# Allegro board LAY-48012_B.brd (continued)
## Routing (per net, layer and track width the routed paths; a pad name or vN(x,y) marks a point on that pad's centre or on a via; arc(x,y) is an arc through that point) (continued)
DAC_SDIN3: length 7.5
  BOTTOM w0.152: R19.2 24.99,32.89 24.99,33.4 26.9,35.31 27.41,35.31 27.71,35 U3.15
DAC_SDIN4: length 6.4
  BOTTOM w0.152: U3.14 28.21,35.26 27.66,35.81 26.64,35.81 24.74,33.91 R20.2
DC_GPIO1: length 3.6
  TOP w0.152: J1.21 22.71,6.16 22.71,8.76 R4.1
DC_I2C_SCL: length 51.3
  BOTTOM w0.152: 39.85,33.78 39.85,32.89 40.74,32 40.74,28.84 42.65,26.94 42.65,17.46 45.84,14.27 45.84,3.45 44.4,2.01 33.02,2.01 31.65,3.38 31.65,5.1 J1.13
DC_I2C_SDA: length 56.2
  BOTTOM w0.152: J1.15 29.65,5.1 29.65,3.35 31.34,1.65 44.68,1.65 46.33,3.3 46.33,14.32 43.03,17.62 43.03,27.09 41.12,29 41.12,33.4 39.85,34.67 39.85,35.56
DC_I2S1_MCLK: length 30.7
  BOTTOM w0.152: R9.1 32.87,28.83 34.26,27.43 39.09,27.43 40.61,25.91 40.61,16.49 43.03,14.08 43.03,6.48 J1.1
DC_I2S1_RX_BCLK: length 35.5
  BOTTOM w0.152: R10.1 35.28,28.45 38.96,28.45 41.25,26.16 41.25,16.76 44.17,13.84 44.17,5.36 43.91,5.1 39.65,5.1 J1.5
DC_I2S1_RX_D0: length 33.7
  BOTTOM w0.152: J1.11 31.5,7.24 27.91,7.24 27.34,7.81 25.06,7.81 22.07,10.79 22.07,27.05 23.34,28.32 23.98,28.32 25.37,29.72 R12.1
DC_I2S1_RX_SYNC: length 46.9
  BOTTOM w0.152: J1.9 34.65,6.1 35.79,7.24 37.06,7.24 37.65,6.65 37.65,3.35 38.07,2.92 43.92,2.92 44.81,3.81 44.81,14.1 41.88,17.02 41.88,26.42 39.22,29.08 35.66,29.08 R11.1
DC_I2S1_TX_BCLK: length 28
  BOTTOM w0.152: R15.1 21.69,32.51 21.69,29.72 19.85,27.88 19.85,6.89 J1.23
DC_I2S1_TX_D0: length 38.7
  BOTTOM w0.152: R17.1 22.33,32.13 22.33,29.46 20.42,27.56 20.42,9.4 21.65,8.17 21.65,3.35 22.07,2.92 25.25,2.92 25.65,3.32 25.65,5.1 J1.17
DC_I2S1_TX_D1: length 34.2
  TOP w0.152: v1(25.88,29.46) v1(24.36,29.46)
  BOTTOM w0.152: R14.1 26.39,29.97 v1(25.88,29.46) ; R18.1 v1(24.36,29.46) 23.72,28.83 23.22,28.83 21.69,27.3 21.69,10.54 24.88,7.35 27.17,7.35 27.65,6.87 27.65,5.1 J1.18
DC_I2S1_TX_D2: length 31.3
  TOP w0.152: v1(25.25,28.83) 23.98,28.83 v1(23.34,29.46)
  BOTTOM w0.152: R19.1 v1(23.34,29.46) 21.25,27.37 21.25,10.35 24.65,6.95 J1.19 ; v1(25.25,28.83) 26.01,28.83 R81.1
DC_I2S1_TX_D3: length 31.7
  BOTTOM w0.152: J1.20 23.65,5.1 23.65,6.93 20.87,9.72 20.87,27.5 22.71,29.34 22.71,31.5 R20.1
DC_I2S1_TX_SYNC: length 40.5
  BOTTOM w0.152: R16.1 21.06,29.97 19.28,28.19 19.28,3.68 20.55,2.41 26.96,2.41 J1.16
DC_INT: length 42
  TOP w0.152: v1(42.39,12.19) v1(46.84,12.19)
  BOTTOM w0.152: J1.3 42.39,7.84 v1(42.39,12.19) ; U3.61 38.17,37.5 R24.1 39.47,36.2 40.11,36.2 41.63,34.67 41.63,29.08 43.41,27.3 43.41,17.91 46.84,14.48 v1(46.84,12.19)
DC_RESET: length 52
  BOTTOM w0.152: J1.7 35.65,5.1 35.65,3.32 36.55,2.41 44.17,2.41 45.31,3.56 45.31,14.26 42.27,17.31 42.27,26.67 39.34,29.59 36.04,29.59 35.15,30.48 35.15,31.24 R26.1 35.41,32.26 34.39,32.26 33.71,32.94 U3.3
MCLK_IN: length 8
  BOTTOM w0.152: R9.2 29.44,28.83 28.42,29.84 28.42,31.37 30.21,33.16 U3.10
MICIN_1: length 10.5
  BOTTOM w0.254: J10.4 57.23,35.79 TVS12.2 R72.1 57.12,38.48 56.87,38.73 R84.2 R71.1 R38.1 56.87,42.42 C41.1
MICIN_2: length 10.9
  BOTTOM w0.254: J11.4 58.46,24.36 TVS13.2 56.58,23.79 R74.1 55.98,23.37 C43.1 54.2,22.99 R73.1 R39.1 R85.2
MUTEC_OUT: length 3.7
  TOP w0.152: v2(28.17,43.31) 27.91,43.56 R33.1
  BOTTOM w0.152: U3.35 28.21,43.35 v2(28.17,43.31)
SCL_CCLK: length 7
  BOTTOM w0.152: R21.2 38.71,32.89 37.82,33.78 36.93,33.78 35.28,35.43 35.28,36.2 35.59,36.5 U3.63
SDA_CDOUT: length 2.3
  BOTTOM w0.152: U3.64 38.4,36 R22.2
N16325068: length 4.9
  TOP w0.381: 25.45,26.16 J5.2 ; J5.2 26.52,25.09 ; J5.2 26.52,27.23 ; 27.39,29.63 FB3.1 ; FB3.1 27.39,30.82 ; FB3.1 26.86,30.23
N16325522: length 3
  BOTTOM w0.152: v2(28.17,40) 28.17,40 U3.25
N16325540: length 3
  BOTTOM w0.152: v2(28.17,41.66) 28.01,41.5 U3.28
N16325558: length 2.4
  BOTTOM w0.152: v2(22.83,41.91) 22.93,42 U3.29
N16325576: length 3.4
  BOTTOM w0.152: v2(23.98,45.97) 23.98,43.94 24.42,43.5 U3.32
N16325594: length 2.3
  BOTTOM w0.152: v2(25.76,45.97) 26.14,46.36 26.9,46.36 27.21,46.04 U3.33
N16325612: length 3
  BOTTOM w0.152: U3.37 29.21,43.79 v2(30.07,42.93)
N16325620: length 3.9
  BOTTOM w0.152: v2(31.85,42.93) 31.09,42.93 29.71,44.3 U3.38
N16325628: length 4.1
  BOTTOM w0.152: U3.41 31.21,44.45 32.74,42.93 v2(33.63,42.93)
N16325638: length 12.6
  BOTTOM w0.254: U3.55 41.24,40.5 42.01,41.27 42.01,44.96 42.65,45.59 C25.1 43.29,47.36 C26.1
N16325678: length 10.5
  BOTTOM w0.254: U3.54 40.98,41 41.5,41.52 C32.1 41.5,46.87 C33.1
N16325718: length 6
  BOTTOM w0.152: C23.1 C24.1 30.45,48.01 30.96,47.5 31.85,47.5 32.21,47.14 U3.43
N16334310: length 2.2
  BOTTOM w0.254: 52.04,68.07 52.04,65.91
N16334338: length 16.3
  BOTTOM w0.254: C51.2 37.54,65.25 40.36,68.07 R49.2
N16334434: length 2.2
  BOTTOM w0.254: R52.1 R53.2 R51.2
N16334446: length 2.4
  BOTTOM w0.254: C54.2 R52.2
N16339295: length 3.1
  BOTTOM w0.254: R58.1 R60.1 C61.2
N16339361: length 4.2
  BOTTOM w0.254: 13.69,36.83 13.69,38.86 13.41,39.14 C65.2
N16339413: length 4.3
  BOTTOM w0.254: C58.2 R57.1 R55.1
N16339465: length 3.3
  BOTTOM w0.254: R59.1 R61.1 C62.2
N16339521: length 3.3
  BOTTOM w0.254: R63.1 R65.1 C66.2
N16339573: length 4.9
  BOTTOM w0.254: R54.1 R56.1 12.93,24.77 13.41,25.25 C57.2
N16343600: length 1.5
  TOP w0.152: D1.A 25.51,10.67 R1.2
N16357095: length 3.5
  TOP w0.152: R83.2 R4.2 R7.1 21.04,10.43 Q2.1
N16357107: length 4.3
  TOP w0.152: R5.1 R2.2 22.71,13.72 22.64,13.78 Q2.3
N16357127: length 7.8
  TOP w0.381: J2.1 32.61,12.57 28.4,12.57 Q1.2 26.83,12.89 R2.1
N16357135: length 5.1
  TOP w0.152: R5.2 26.07,14.79 Q1.1 28.23,14.79 29.06,15.62 C13.1
N16357758: length 5.4
  TOP w0.152: U1.4 34.33,21.9 34.77,21.46 R3.2 R6.1
N16357876: length 10.3
  TOP w0.381: C9.1 39.08,22.23 ; C9.1 37.58,22.23 ; C9.1 38.33,21.6 ; U1.3 36.89,21.9 ; U1.3 36.2,22.46 ; U1.3 35.51,21.9 ; 39.98,22.1 C10.1 40.61,22.61 ; 38.15,19.81 J13.2 ; J13.2 39.22,20.88 ; J13.2 40.28,19.81 ; U1.1 36.89,20.01 ; U1.1 35.51,20.01 ; U1.1 36.2,19.45
N16358335: length 10.2
  TOP w0.381: 21.73,20.72 U2.3 ; U2.3 22.67,20.72 ; U2.3 22.2,21.5 ; 27.23,22.1 J14.2 ; J14.2 28.3,23.17 ; J14.2 29.36,22.1 ; J14.2 28.3,21.03 ; C15.1 25.76,21.21 ; C15.1 26.64,22.1 ; C15.1 C14.1 ; C14.1 24.24,22.1 ; C14.1 24.87,21.21
N16404329: length 5.8
  BOTTOM w0.254: C69.2 R68.1 R66.1
N16404657: length 3.3
  BOTTOM w0.254: 15.09,66.93 C70.2
N16406078: length 8.4
  TOP w0.152: TP1.1 18.64,6.35 19.9,5.1 21.68,5.1 22.65,4.12 J1.22
N16452852: length 6.5
  TOP w0.254: v1(51.41,36.32) J10.2
  BOTTOM w0.254: v1(51.41,36.32) 55.47,36.32 R72.2
N16452871: length 6.4
  TOP w0.254: v1(51.54,39.62) 51.41,39.75 J10.3
  BOTTOM w0.254: v1(51.54,39.62) 52.43,39.62 52.68,39.88 R71.2
N16456970: length 12.4
  TOP w0.254: TP18.1 16.23,28.19 12.55,31.88 8.74,31.88 8.43,31.57 J6.5
N16456974: length 10.2
  TOP w0.254: J6.6 8.43,22.02 9.02,21.44 13.28,21.44 15.21,23.37 TP19.1
N16456978: length 16.6
  TOP w0.254: J6.4 4.31,29.23 7.59,32.51 13.44,32.51 TP20.1
N16457195: length 12.4
  TOP w0.254: TP21.1 16.23,39.62 12.55,43.31 8.74,43.31 8.43,43 J7.5
N16457199: length 9.9
  TOP w0.254: J7.6 8.43,33.58 8.86,33.15 13.44,33.15 15.09,34.8 TP22.1
N16457203: length 16.6
  TOP w0.254: J7.4 4.82,40.66 8.1,43.94 13.44,43.94 TP23.1
N16457422: length 12.4
  TOP w0.254: J8.5 8.43,54.43 8.74,54.74 12.55,54.74 16.23,51.05 TP24.1
N16457426: length 9.9
  TOP w0.254: J8.6 8.43,45.01 8.86,44.58 14.58,44.58 TP25.1
N16457430: length 16.6
  TOP w0.254: J8.4 4.44,52.09 7.72,55.37 13.44,55.37 TP26.1
N16457651: length 12.4
  TOP w0.254: TP27.1 16.23,62.48 12.55,66.17 8.74,66.17 8.43,65.86 J9.5
N16457655: length 9.9
  TOP w0.254: TP28.1 14.58,56.01 8.86,56.01 8.43,56.44 J9.6
N16457659: length 16.6
  TOP w0.254: TP29.1 13.44,66.8 7.59,66.8 4.31,63.52 J9.4
N16458067: length 16.6
  TOP w0.254: J12.4 58.37,58.65 55.09,55.37 49.5,55.37 TP32.1
N16458071: length 10
  TOP w0.254: J12.6 54.51,65.74 53.95,66.29 48.49,66.29 TP31.1
N16458075: length 12.4
  TOP w0.254: J12.5 54.51,56.31 54.2,56.01 50.39,56.01 46.71,59.69 TP30.1
N16458447: length 9.4
  TOP w0.254: J11.3 v1(51.41,28.7)
  BOTTOM w0.254: R74.2 56.49,27.05 54.84,28.7 v1(51.41,28.7)
N16458491: length 3.3
  TOP w0.254: v1(52.43,21.21) 52.43,22.23 51.41,23.24 J11.2
  BOTTOM w0.254: v1(52.43,21.21) R73.2
N16475768: length 2
  BOTTOM w0.254: 52.04,53.97 52.04,56.01
N16475784: length 11.9
  BOTTOM w0.254: C73.2 48.26,58.78 R77.2
N16475838: length 2
  BOTTOM w0.254: R80.1 R79.2 R78.2
N16475850: length 2.2
  BOTTOM w0.254: C74.2 R80.2
N16477331: length 16.8
  TOP w0.254: TP35.1 47.73,46.74 50.77,43.69 55.47,43.69 59.01,47.22 J15.4
N16477335: length 9.9
  TOP w0.254: J15.6 54.51,54.31 54.08,54.74 48.36,54.74 TP34.1
N16477339: length 12.5
  TOP w0.254: TP33.1 46.71,48.51 51.03,44.2 53.7,44.2 53.95,44.45 53.95,45.67 J15.5
N16544253: length 70.5
  TOP w0.254: P1.1 29.44,69.47 30.96,67.94 54.58,67.94 56.62,65.91 v1(56.62,62.86)
  BOTTOM w0.254: R84.1 58.9,39.88 58.9,46.23 56.62,48.51 v1(56.62,62.86)
N16544784: length 1.9
  BOTTOM w0.254: R85.1 54.2,17.78 P2.1

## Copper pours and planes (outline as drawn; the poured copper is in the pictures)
AGND on TOP: 62.33,71.63 62.71,71.25 62.71,22.48 62.46,22.23 57.25,22.23 55.98,20.95 55.98,16.38 55.6,16 46.33,16 44.42,17.91 44.42,28.19 42.77,29.84 42.77,35.05 40.11,37.72 34.52,37.72 32.99,39.24 27.91,39.24 27.28,39.88 21.18,39.88 20.29,38.99 20.29,30.86 18.01,28.58 18.01,22.1 16.36,20.45 7.72,20.45 6.2,21.97 0.36,21.97 0.23,22.1 0.23,71.25 0.61,71.63 ; 1 cut-out
AGND on BOTTOM: 62.33,71.63 62.71,71.25 62.71,22.48 62.46,22.23 57.25,22.23 55.98,20.95 55.98,16.38 55.6,16 50.65,16 50.52,16.13 50.52,17.4 50.14,17.78 47.35,17.78 46.33,18.8 44.55,18.8 44.42,18.92 44.42,28.32 42.77,29.97 42.77,35.05 40.61,37.21 38.96,37.21 38.46,37.72 34.52,37.72 32.99,39.24 27.91,39.24 27.28,39.88 21.18,39.88 18.01,36.7 18.01,22.1 16.36,20.45 7.72,20.45 6.2,21.97 0.36,21.97 0.23,22.1 0.23,71.25 0.61,71.63 ; 6 cut-outs
AGND on L2_GND1: 62.33,71.63 62.71,71.25 62.71,22.48 62.46,22.23 57.25,22.23 55.98,20.95 55.98,16.38 54.58,14.99 47.35,14.99 44.42,17.91 44.42,28.32 42.9,29.84 42.9,34.92 40.61,37.21 38.96,37.21 38.46,37.72 34.52,37.72 32.99,39.24 27.91,39.24 27.28,39.88 21.18,39.88 20.29,38.99 20.29,30.86 18.01,28.58 18.01,22.1 16.36,20.45 7.85,20.45 6.2,22.1 0.48,22.1 0.23,22.35 0.23,71.12 0.74,71.63 ; 1 cut-out
AGND on L3_GND2: 62.33,71.63 62.71,71.25 62.71,22.48 62.46,22.23 57.25,22.23 55.98,20.95 55.98,16.38 55.6,16 50.65,16 50.52,16.13 50.52,17.53 50.27,17.78 47.35,17.78 46.33,18.8 44.68,18.8 44.42,19.05 44.42,28.32 42.9,29.84 42.9,34.92 40.11,37.72 34.52,37.72 32.99,39.24 27.91,39.24 27.28,39.88 21.18,39.88 20.29,38.99 20.29,30.86 18.01,28.58 18.01,22.1 16.36,20.45 7.85,20.45 6.2,22.1 0.36,22.1 0.23,22.23 0.23,71.25 0.61,71.63
GND on TOP: 21.31,39.62 27.15,39.62 27.79,38.99 32.87,38.99 34.39,37.47 39.98,37.47 42.52,34.92 42.52,29.72 44.17,28.07 44.17,17.65 46.2,15.62 55.98,15.62 56.36,16 56.36,20.83 57.38,21.84 62.59,21.84 62.71,21.72 62.71,10.79 62.46,10.54 47.45,10.54 47.45,0.51 15.47,0.51 15.47,10.54 0.23,10.54 0.23,21.59 0.36,21.72 6.07,21.72 7.59,20.19 16.48,20.19 18.26,21.97 18.26,28.32 20.55,30.61 20.55,38.86 ; 3 cut-outs
GND on BOTTOM: 34.39,14.86 32.74,13.21 27.03,13.21 27.03,10.29 28.04,9.27 28.04,8.38 27.79,8.13 25.76,8.13 22.45,11.43 22.45,26.92 23.47,27.94 24.23,27.94 25.63,29.34 28.68,29.34 29.69,28.32 32.11,28.32 32.17,28.26 32.8,28.26 34.39,26.67
GND on BOTTOM: 26.39,39.5 27.15,39.5 27.66,38.99 32.87,38.99 34.39,37.47 35.28,37.47 35.41,37.34 35.41,36.83 34.9,36.32 34.9,35.43 34.65,35.18 29.06,35.18 27.53,36.7 27.53,37.72 26.9,38.35 26.39,38.35 26.26,38.48 26.26,39.37
GND on BOTTOM: 16.48,20.19 18.01,21.72 18.64,21.72 18.77,21.59 18.77,3.3 20.42,1.65 30.2,1.65 30.71,1.14 44.93,1.14 46.84,3.05 46.84,15.11 44.04,17.91 44.04,18.41 44.17,18.54 46.08,18.54 47.22,17.4 50.14,17.4 50.27,17.27 50.27,15.75 50.39,15.62 55.98,15.62 56.36,16 56.36,20.7 57.51,21.84 62.59,21.84 62.71,21.72 62.71,10.92 62.33,10.54 47.35,10.54 47.35,10.54 47.35,0.89 47.09,0.64 15.72,0.64 15.6,0.76 15.6,10.41 15.47,10.54 0.23,10.54 0.23,21.59 0.36,21.72 6.07,21.72 7.59,20.19
GND on L2_GND1: 62.59,10.54 47.45,10.54 47.45,0.61 47.35,0.51 15.47,0.51 15.47,10.54 0.36,10.54 0.23,10.67 0.23,21.59 0.36,21.72 6.07,21.72 7.59,20.19 16.48,20.19 18.26,21.97 18.26,28.32 20.55,30.61 20.55,38.86 21.31,39.62 27.15,39.62 27.79,38.99 32.87,38.99 34.39,37.47 39.98,37.47 42.52,34.92 42.52,29.72 44.17,28.07 44.17,17.53 47.09,14.61 54.84,14.61 56.36,16.13 56.36,20.83 57.38,21.84 62.59,21.84 62.71,21.72 62.71,10.67 ; 1 cut-out
GND on L3_GND2: 62.46,10.54 47.45,10.54 47.45,0.51 15.47,0.51 15.47,10.54 0.36,10.54 0.36,21.59 0.48,21.72 6.07,21.72 7.59,20.19 16.48,20.19 18.26,21.97 18.26,28.32 20.55,30.61 20.55,38.86 21.31,39.62 27.03,39.62 27.66,38.99 32.87,38.99 34.39,37.47 39.98,37.47 42.52,34.92 42.52,29.72 44.17,28.07 44.17,18.8 44.42,18.54 46.08,18.54 47.22,17.4 50.14,17.4 50.27,17.27 50.27,15.75 50.39,15.62 55.98,15.62 56.36,16 56.36,20.7 57.51,21.84 62.59,21.84 62.71,21.72 62.71,10.79 ; 1 cut-out
P1V8 on TOP: 37.44,12.32 37.44,8.26 37.19,8 36.55,8 34.65,9.91 34.65,12.32 34.77,12.45 37.31,12.45
P1V8 on BOTTOM: 27.53,19.81 33.25,19.81 33.44,19.62 33.44,16.45 37.44,12.45 37.44,8.51 37.31,8.38 29.31,8.38 27.28,10.41 27.28,19.56
P1V8 on L2_GND1: 39.98,8.26 39.98,3.3 39.6,2.92 31.47,2.92 31.34,3.05 31.34,8.13 31.47,8.26 33.63,8.26 34.65,9.27 34.65,12.32 34.77,12.45 37.57,12.45 37.69,12.32 37.69,10.54
P1V8_S on TOP: 21.95,22.23 21.82,22.1 21.31,22.1 20.93,21.72 20.93,19.68 21.31,19.3 24.23,19.3 24.36,19.18 24.36,16.13 24.23,16 18.77,16 18.64,16.13 18.64,19.56 19.02,19.94 19.02,24.38 19.15,24.51 21.82,24.51 21.95,24.38
P3V3 on TOP: 41.88,12.83 41.88,8.26 42.52,7.62 44.42,7.62 44.68,7.37 44.68,2.92 44.55,2.79 37.57,2.79 37.44,2.92 37.44,7.87 37.57,8 38.71,8 39.85,9.14 39.85,12.83 39.98,12.95 41.76,12.95
P3V3 on BOTTOM: 41.63,8.13 37.82,8.13 37.69,8.26 37.69,12.57 33.88,16.38 33.88,22.99 36.68,25.78 36.68,27.18 36.8,27.3 39.34,27.3 39.47,27.18 39.47,22.35 37.82,20.7 37.82,16.51 38.33,16 40.23,16 41.88,14.35 41.88,8.38
P3V3_S on TOP: 32.74,22.61 32.74,21.08 32.87,20.95 34.14,20.95 34.26,20.83 34.26,18.92 34.14,18.8 30.07,18.8 29.95,18.92 29.95,23.62 31.34,25.02 31.34,27.56 31.6,27.81 33.76,27.81 34.01,27.56 34.01,22.99 33.88,22.86 32.99,22.86
P5V on TOP: 35.79,8.13 35.79,2.92 35.66,2.79 27.53,2.79 27.41,2.92 27.41,7.62 27.53,7.75 29.31,7.75 29.44,7.87 29.44,11.68 29.69,11.94 34.26,11.94 34.39,11.81 34.39,9.53
P5V_S on TOP: 50.27,17.27 50.27,15.11 50.14,14.99 38.71,14.99 38.07,14.35 32.36,14.35 31.09,13.08 29.69,13.08 29.44,13.34 29.44,14.61 29.69,14.86 31.09,14.86 31.47,15.24 31.47,15.88 31.6,16 37.44,16 37.57,16.13 37.57,18.41 37.69,18.54 46.08,18.54 47.22,17.4 50.14,17.4
VCC_1V8 on TOP: 19.15,24.89 24.61,24.89 24.87,25.15 24.87,27.3 24.61,27.56 19.15,27.56 19.02,27.43 19.02,25.02
VCC_1V8 on BOTTOM: 26.77,16.38 26.64,16.26 24.36,16.26 24.23,16.38 24.23,20.7 22.71,22.23 22.71,27.3 22.83,27.43 25.25,27.43 25.37,27.3 25.37,25.4 26.77,24
VCC_3V3 on TOP: 36.68,29.46 36.68,24.89 36.55,24.77 34.39,24.77 34.26,24.89 34.26,27.81 34.01,28.07 31.34,28.07 30.96,27.69 30.96,25.02 30.71,24.77 28.3,24.77 28.04,25.02 28.04,28.7 28.42,29.08 29.69,29.08 30.2,29.59 36.55,29.59
VCC_CODEC_5V0 on TOP: 53.06,20.07 53.19,19.94 53.19,18.16 52.93,17.91 47.73,17.91 47.47,18.16 47.47,19.18 48.36,20.07
VCC_CODEC_5V0 on L2_GND1: 47.09,18.03 45.95,19.18 45.95,40.26 44.3,41.91 31.09,41.91 30.84,42.16 30.84,49.15 32.11,50.42 48.11,50.42 55.09,43.43 55.09,18.92 54.2,18.03
VCC_CODEC_IO on L2_GND1: 30.07,29.21 29.31,29.97 29.31,31.75 32.61,35.05 37.95,35.05 40.23,32.77 40.23,29.84 39.6,29.21
N16325068 on TOP: 22.2,31.24 22.33,31.37 27.79,31.37 27.91,31.24 27.91,28.96 27.66,28.7 27.66,25.02 27.53,24.89 25.25,24.89 25.12,25.02 25.12,27.56 24.74,27.94 22.33,27.94 22.2,28.07
N16357876 on TOP: 37.57,18.8 37.31,19.05 35.28,19.05 35.15,19.18 35.15,22.61 35.41,22.86 41.25,22.86 41.38,22.73 41.38,19.18 41,18.8
N16358335 on TOP: 24.23,22.35 26.39,22.35 27.53,23.5 29.18,23.5 29.57,23.11 29.57,20.07 29.18,19.68 21.44,19.68 21.31,19.81 21.31,21.59 21.44,21.72 23.6,21.72

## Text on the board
BOTTOM: 170-48012 REV B | 4 | L4_SS
Board Geometry/Soldermask Bottom: 8 | SOLDERMASK BOTTOM
Ref Des/Silkscreen Bottom: 1 | 10 | SILKSCREEN BOTTOM
TOP: 1 | L1_PS
Board Geometry/Soldermask Top: 5 | SOLDERMASK TOP
Ref Des/Silkscreen Top: LINE5&6 OUTPUT | LINE7&8 OUTPUT | LINE3&4 OUTPUT | LINE1&2 | OUTPUT | MIC2 INPUT | Stereo INPUT2 | Stereo INPUT1 | MIC1 INPUT | 7 | SILKSCREEN TOP | AUD-EXP-42448
DIMENSION: PRIMARY DATUM | GRID ORIGIN
User.6: ASY 501-1-00596_B1 .ZIP CONSISTS OF FOLLOWING ASSEMBLY DATA | 501-1-00596_B1_PNP .TXT -  PICK AND PLACE DATA | 501-1-00596_B1_PMB .ART -  BOTTOM PASTE (BOTTOM PASTE) | PCB SECONDARY SIDE | MAXIMUM HEIGHT 5.50 MM | PCB PRIMARY SIDE | MAXIMUM HEIGHT 16.00 MM | PCB THICKNESS 1.6MM | NOTES:          UNLESS OTHERWISE SPECIFIED. | CAUTION :       COMPONENTS ARE SUBJECT TO DAMAGE BY STATIC ELECTRICITY. | 6) STICK TO THE BACKING REQUIREMENT AS PER CLASS RECOMMENEDATION. | 7) "FIDUCIAL'S  WILL NOT BE THRU OPEN, IT SHOULD BE HALFETCH". | 4) APERTURES MAY BE MODIFIED TO BEST FIT VVDN REQUIREMENT. | 5) ASSEMBLY SHALL BE ELCECTRICALLY TESTED. | 3) SOLDER PASTE TOOLING SHOULD BE MADE USING 501-1-00596_B1_PMB.ART FOR SECONDARY SIDE. | 2) LABELS SHALL NOT TO BE PLACED OVER EXPOSED COPPER AND METAL. | 1) SOLDER AND ASSEMBLE AS PER INDUSTRY WORKMANSHIP STANDARDS. | ASY-29941
User.8: ___ COMPANY PUBLIC | ___ COMPANY INTERNAL | ___ COMPANY CONFIDENTIAL | THIS DOCUMENT CONTAINS INFORMATION | PROPRIETARY TO NXP AND SHALL NOT | BE USED FOR ENGINEERING DESIGN | PROCUREMENT OR MANUFACTURE IN WHOLE | OR IN PART WITHOUT THE CONSENT OF | NXP. | 6501 WILLIAM CANNON DRIVE WEST  AUSTIN, TEXAS 78735 USA | X | VVDN | 30-11-17 | 10-07-17 | 1 | X.X. | A1 | B1 | SOLDERMASK COLOUR CHANGED | SCHEMATIC CHANGES UPDATED | LAY-29941 | 170-29941 | IMX-AUD-IO | PRINTED WIRING BOARD | NXP SEMICONDUCTORS
User.9: 1 | PCB EDGE | ASSEMBLY TOP
User.10: PART NO:501-1-00596 | PART NAME: | DESIGNED FOR: NXP | AUDIO IO CARD | REV:C1 | LAYER: | SHEET 2 OF 3 | PANEL DRAWING TOP | TOLERANCE + / - 0.1MM | ALL DIMENSIONS ARE IN MM
User.11: MH1 | MH3 | TP24 | J3 | MH4 | MH2 | J13 | J20 | J12 | J15 | J11 | J19 | J17 | J14 | J16 | TP30 | TP39 | TP33 | TP29 | TP40 | TP31 | TP32 | TP36 | TP34 | J18 | TP41 | TP37 | TP35 | TP25 | TP38 | * | TP23 | T*
User.12: * | T* | ___ COMPANY PUBLIC | ___ COMPANY INTERNAL | ___ COMPANY CONFIDENTIAL | THIS DOCUMENT CONTAINS INFORMATION | PROPRIETARY TO NXP AND SHALL NOT | BE USED FOR ENGINEERING DESIGN | PROCUREMENT OR MANUFACTURE IN WHOLE | OR IN PART WITHOUT THE CONSENT OF | NXP. | 6501 WILLIAM CANNON DRIVE WEST  AUSTIN, TEXAS 78735 USA | X | VVDN | 30-11-17 | 10-07-17 | 1 | X.X. | ASY 501-1-00596_B1 .ZIP CONSISTS OF FOLLOWING ASSEMBLY DATA | 501-1-00596_B1_PNP .TXT -  PICK AND PLACE DATA | 501-1-00596_B1_PMB .ART -  BOTTOM PASTE (BOTTOM PASTE) | PCB SECONDARY SIDE | MAXIMUM HEIGHT 5.50 MM | PCB PRIMARY SIDE | MAXIMUM HEIGHT 16.00 MM | PCB THICKNESS 1.6MM | NOTES:          UNLESS OTHERWISE SPECIFIED. | CAUTION :       COMPONENTS ARE SUBJECT TO DAMAGE BY STATIC ELECTRICITY. | 6) STICK TO THE BACKING REQUIREMENT AS PER CLASS RECOMMENEDATION. | 7) "FIDUCIAL'S  WILL NOT BE THRU OPEN, IT SHOULD BE HALFETCH". | 4) APERTURES MAY BE MODIFIED TO BEST FIT VVDN REQUIREMENT. | 5) ASSEMBLY SHALL BE ELCECTRICALLY TESTED. | 3) SOLDER PASTE TOOLING SHOULD BE MADE USING 501-1-00596_B1_PMB.ART FOR SECONDARY SIDE. | 2) LABELS SHALL NOT TO BE PLACED OVER EXPOSED COPPER AND METAL. | 1) SOLDER AND ASSEMBLE AS PER INDUSTRY WORKMANSHIP STANDARDS. | A1 | B1 | SOLDERMASK COLOUR CHANGED | SCHEMATIC CHANGES UPDATED | LAY-29941 | 170-29941 | ASY-29941 | IMX-AUD-IO | PRINTED WIRING BOARD | NXP SEMICONDUCTORS
User.18: PANEL DRAWING BOTTOM | SHEET 2 OF 3 | LAYER: | REV:C1 | AUDIO IO CARD | DESIGNED FOR: NXP | PART NAME: | PART NO:501-1-00596 | ALL DIMENSIONS ARE IN MM | TOLERANCE + / - 0.1MM
User.29: OF10
User.33: THIS FAB_VIAFILL.ART SHOWS LOCATIONS OF VIA-IN-PAD TO BE FILLED. | 2
User.36: 1
User.37: ASY-29941 | PCB THICKNESS 1.6MM
User.39: LAYER STACKUP DETAILS | FR-4 Tg 170 Deg C Td 340 Deg C | CONSTRUCTION | SOLDER MASK | DETAIL A | 0.8 mil | L1 Cu, 1 OZ (Finished) | 4.5 mil, PREPEG | 46.44 mil, CORE | L2 Cu, 1 OZ | L3 Cu, 1 OZ | L4 Cu, 1 OZ (Finished) | DETAIL B | 63 MILS | TOL. +\- 10% | 50 OHMS | 6 MILS | 29. THIS BOARD USES VIA-IN-PAD: SEE FAB_VIAFILL.ART | 28. VENDOR SHOULD NOT MODIFY ARTWORK EXCEPT FOR PROCESS CONTROL. | 22. MARK WITH VENDOR LOGO AND DATE CODE. MUST NOT BE ETCHED. | 23. BOARD THICKNESS WHICH EVER MENTIONED IS WITH PLATING. | A. ALL VIAS USING X.1 DRILL SIZES ARE TO BE FILLED WITH NON-CONDUCTIVE VIA FILL. | B. OVERPLATE THE FILLED VIA AND APPLY FINISH METAL TREATMENT. | C. DIMPLE OR PROTRUSION ON VIA-IN-PADS MUST BE NO GREATER THAN .001". | LACKWERKE-PETERS PP2795 OR EQUIVALENT AND MADE PLANAR TO THE PADS. | FAB VENDOR SHOULD PROVIDE 5MM BREAKAWAY STRIP AROUND THE PANEL. | 4NOS OF FIDUCIAL ON TOP SIDE,4NOS OF FIDUCIAL ON BOTTOM SIDE AND 4NOS OF 3.2MM TOOLING HOLES | ARE REQUIRED ON BREAKAWAY STRIP. | 19 | 16 | 29 | 8
User.40: FAB DRAWING
User.41: TOP SOLDER
User.42: BOTTOM SOLDER
User.43: TOP PASTE
User.44: FIDUCIAL'S  WILL NOT BE THRU OPEN IT SHOULD BE HALFETCH | BOTTOM PASTE
User.45: L1_TOP | L3_GND2 | L4_BOTTOM | TOP SILK | BOTTOM SILK | 03-26-21 | X.X. | B | ADD R83(DNP) FOR 3V3 POWER | 2 | FIGURE | FINISHED_SIZE | 10.0 | 10.1 | 30.0 | 32.0 | 40.0 | 139.0 | 59.0 | 138.0 | 59.0x20.0 | DRILL CHART: TOP to BOTTOM | ALL UNITS ARE IN MILS | TOLERANCE_DRILL | +3.0/-3.0 | +0.0/-10.1 | +2.0/-2.0 | PLATED | NON-PLATED | QTY | 313 | 25 | 4 | 24 | 15 | 16
